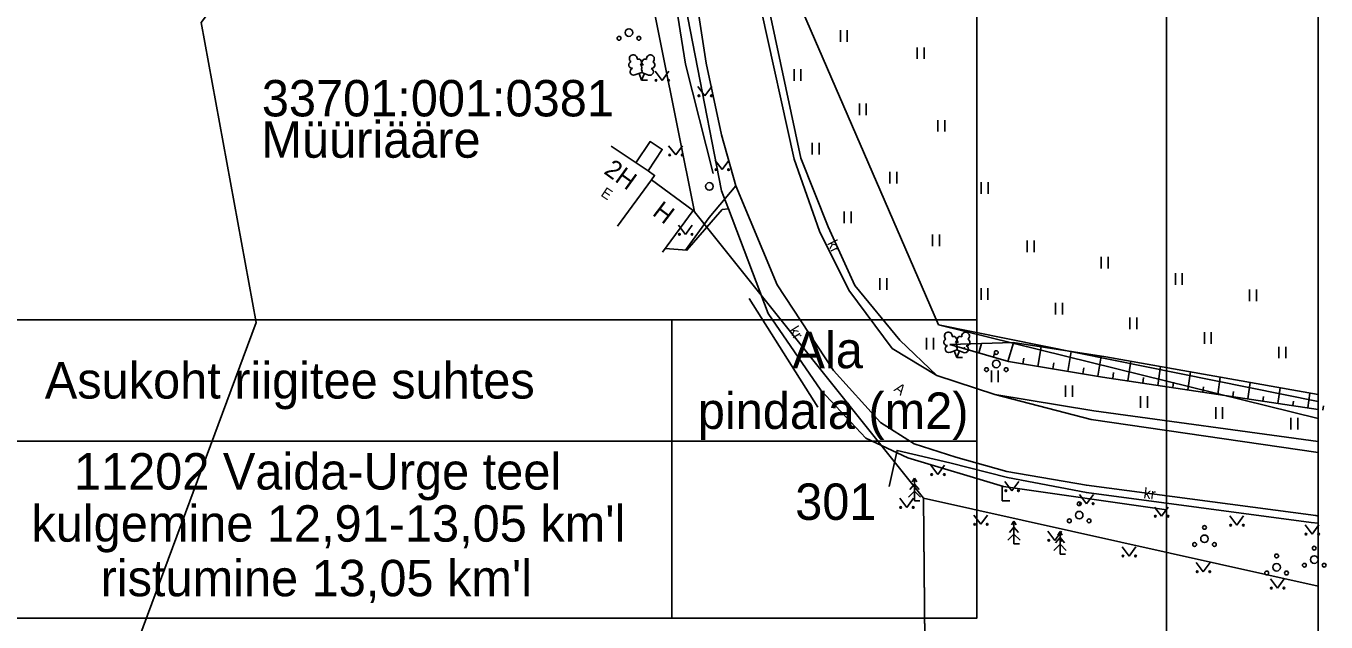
# Model space of a CAD drawing. Extents: x 554947 to 555436, y 6564938 to 6565792.
# Drawn here: x 555307.9 to 555393.6, y 6565441.5 to 6565480.8 of the extents above; entities that cross this region are included whole.
import ezdxf

# ---------------------------------------------------------------- set-up
doc = ezdxf.new("R2010")
doc.units = 0
for name, color, linetype in [('AED', 7, 'Continuous'), ('HALJASTUS', 7, 'Continuous'), ('HOONE', 7, 'Continuous'), ('HOONEDET', 7, 'Continuous'), ('PIIR', 7, 'Continuous'), ('POST', 7, 'Continuous'), ('PR_SIDE', 7, 'Continuous'), ('PUU', 7, 'Continuous'), ('RELJEEF', 7, 'Continuous'), ('TEE', 7, 'Continuous'), ('VORMISTUS_3', 7, 'Continuous')]:
    doc.layers.add(name, color=color, linetype=linetype)

msp = doc.modelspace()

# ---------------------------------------------------------------- linework, layer by layer
at = {"layer": 'AED'}
msp.add_line((555360.091, 6565455.665), (555355.569, 6565462.842), dxfattribs=at)
msp.add_lwpolyline([(555353.187, 6565471.073), (555351.365, 6565478.297), (555349.912, 6565487.399), (555348.203, 6565498.717)], dxfattribs=at)
at = {"layer": 'HALJASTUS'}
for p, q in [((555361.573, 6565480.529), (555361.573, 6565479.768)), ((555362.028, 6565480.529), (555362.028, 6565479.768)), ((555366.634, 6565479.397), (555366.634, 6565478.636)), ((555367.09, 6565479.397), (555367.09, 6565478.636)), ((555358.52, 6565477.955), (555358.52, 6565477.194)), ((555358.975, 6565477.955), (555358.975, 6565477.194)), ((555349.36, 6565477.827), (555349.824, 6565477.22)), ((555349.824, 6565477.22), (555350.269, 6565477.827)), ((555352.185, 6565476.814), (555352.649, 6565476.207)), ((555352.649, 6565476.207), (555353.094, 6565476.814)), ((555362.828, 6565475.689), (555362.828, 6565474.928)), ((555363.283, 6565475.689), (555363.283, 6565474.928)), ((555368.005, 6565474.604), (555368.005, 6565473.843)), ((555368.46, 6565474.604), (555368.46, 6565473.843)), ((555350.258, 6565472.908), (555350.722, 6565472.302)), ((555350.722, 6565472.302), (555351.167, 6565472.908)), ((555359.727, 6565473.103), (555359.727, 6565472.342)), ((555360.182, 6565473.103), (555360.182, 6565472.342)), ((555353.315, 6565471.943), (555353.779, 6565471.336)), ((555353.779, 6565471.336), (555354.224, 6565471.943)), ((555364.839, 6565471.191), (555364.839, 6565470.43)), ((555365.294, 6565471.191), (555365.294, 6565470.43)), ((555370.858, 6565470.499), (555370.858, 6565469.738)), ((555371.313, 6565470.499), (555371.313, 6565469.738)), ((555361.828, 6565468.572), (555361.828, 6565467.811)), ((555362.283, 6565468.572), (555362.283, 6565467.811)), ((555350.905, 6565467.676), (555351.368, 6565467.069)), ((555351.368, 6565467.069), (555351.814, 6565467.676)), ((555367.645, 6565467.053), (555367.645, 6565466.292)), ((555368.1, 6565467.053), (555368.1, 6565466.292)), ((555373.889, 6565466.657), (555373.889, 6565465.895)), ((555374.344, 6565466.657), (555374.344, 6565465.895)), ((555378.771, 6565465.579), (555378.771, 6565464.817)), ((555379.226, 6565465.579), (555379.226, 6565464.817)), ((555383.654, 6565464.5), (555383.654, 6565463.739)), ((555384.109, 6565464.5), (555384.109, 6565463.739)), ((555364.172, 6565464.177), (555364.172, 6565463.416)), ((555364.627, 6565464.177), (555364.627, 6565463.416)), ((555370.845, 6565463.51), (555370.845, 6565462.749)), ((555371.3, 6565463.51), (555371.3, 6565462.749)), ((555388.536, 6565463.422), (555388.536, 6565462.661)), ((555388.991, 6565463.422), (555388.991, 6565462.661)), ((555375.752, 6565462.547), (555375.752, 6565461.786)), ((555376.207, 6565462.547), (555376.207, 6565461.786)), ((555380.658, 6565461.583), (555380.658, 6565460.822)), ((555381.113, 6565461.583), (555381.113, 6565460.822)), ((555367.254, 6565460.24), (555367.254, 6565459.479)), ((555367.709, 6565460.24), (555367.709, 6565459.479)), ((555385.564, 6565460.62), (555385.564, 6565459.859)), ((555386.019, 6565460.62), (555386.019, 6565459.859)), ((555390.47, 6565459.657), (555390.47, 6565458.896)), ((555390.926, 6565459.657), (555390.926, 6565458.896)), ((555371.525, 6565458.083), (555371.525, 6565457.321)), ((555371.98, 6565458.083), (555371.98, 6565457.321)), ((555376.419, 6565457.107), (555376.419, 6565456.346)), ((555376.874, 6565457.107), (555376.874, 6565456.346)), ((555381.367, 6565456.392), (555381.367, 6565455.63)), ((555381.822, 6565456.392), (555381.822, 6565455.63)), ((555386.316, 6565455.676), (555386.316, 6565454.915)), ((555386.771, 6565455.676), (555386.771, 6565454.915)), ((555391.265, 6565454.961), (555391.265, 6565454.2)), ((555391.72, 6565454.961), (555391.72, 6565454.2)), ((555367.533, 6565451.84), (555367.997, 6565451.233)), ((555367.997, 6565451.233), (555368.442, 6565451.84)), ((555372.249, 6565450.508), (555372.249, 6565449.508)), ((555372.419, 6565450.775), (555372.882, 6565450.168)), ((555372.882, 6565450.168), (555373.328, 6565450.775)), ((555365.487, 6565449.67), (555365.951, 6565449.064)), ((555365.951, 6565449.064), (555366.396, 6565449.67)), ((555377.344, 6565449.916), (555377.807, 6565449.309)), ((555377.807, 6565449.309), (555378.253, 6565449.916)), ((555372.249, 6565449.508), (555372.749, 6565449.508)), ((555382.275, 6565449.089), (555382.738, 6565448.482)), ((555382.738, 6565448.482), (555383.184, 6565449.089)), ((555370.362, 6565448.557), (555370.825, 6565447.95)), ((555370.825, 6565447.95), (555371.271, 6565448.557)), ((555387.24, 6565448.5), (555387.703, 6565447.893)), ((555387.703, 6565447.893), (555388.149, 6565448.5)), ((555375.249, 6565447.5), (555375.712, 6565446.893)), ((555375.712, 6565446.893), (555376.158, 6565447.5)), ((555392.205, 6565447.911), (555392.669, 6565447.304)), ((555392.669, 6565447.304), (555393.114, 6565447.911)), ((555380.141, 6565446.467), (555380.604, 6565445.86)), ((555380.604, 6565445.86), (555381.05, 6565446.467)), ((555385.033, 6565445.433), (555385.496, 6565444.826)), ((555385.496, 6565444.826), (555385.942, 6565445.433)), ((555389.914, 6565444.349), (555390.377, 6565443.742)), ((555390.377, 6565443.742), (555390.823, 6565444.349))]:
    msp.add_line(p, q, dxfattribs=at)
for centre in [(555349.423, 6565477.22), (555350.251, 6565477.22), (555352.248, 6565476.207), (555353.077, 6565476.207), (555350.321, 6565472.302), (555351.15, 6565472.302), (555353.378, 6565471.336), (555354.207, 6565471.336), (555350.967, 6565467.069), (555351.796, 6565467.069), (555367.596, 6565451.233), (555368.425, 6565451.233), (555372.481, 6565450.168), (555373.31, 6565450.168), (555365.55, 6565449.064), (555366.378, 6565449.064), (555377.406, 6565449.309), (555378.235, 6565449.309), (555370.424, 6565447.95), (555371.253, 6565447.95), (555382.337, 6565448.482), (555383.166, 6565448.482), (555387.302, 6565447.893), (555388.131, 6565447.893), (555392.268, 6565447.304), (555393.096, 6565447.304), (555375.311, 6565446.893), (555376.14, 6565446.893), (555380.203, 6565445.86), (555381.032, 6565445.86), (555385.095, 6565444.826), (555385.924, 6565444.826), (555389.976, 6565443.742), (555390.805, 6565443.742)]:
    msp.add_circle(centre, 0.055, dxfattribs=at)
at = {"layer": 'HOONE'}
msp.add_line((555346.887, 6565467.616), (555349.13, 6565470.659), dxfattribs=at)
msp.add_lwpolyline([(555346.471, 6565472.875), (555348.897, 6565471.26), (555349.328, 6565470.958), (555349.13, 6565470.659), (555351.876, 6565468.634), (555349.848, 6565465.883)], dxfattribs=at)
at = {"layer": 'HOONEDET'}
msp.add_lwpolyline([(555348.897, 6565471.26), (555349.833, 6565472.665), (555349.029, 6565473.189), (555348.099, 6565471.792)], dxfattribs=at)
at = {"layer": 'PIIR'}
for points in [[(555393.069, 6565456.052), (555368.05, 6565461.11), (555358.8, 6565482.45), (555353.12, 6565523.87), (555393.069, 6565560.972)], [(555393.069, 6565443.872), (555367.06, 6565449.68), (555351.96, 6565468.55), (555343.14, 6565512.46), (555353.12, 6565523.87), (555358.8, 6565482.45), (555368.05, 6565461.11), (555393.069, 6565454.923)], [(555393.069, 6565454.923), (555368.05, 6565461.11), (555393.069, 6565456.052)], [(555367.477, 6565404.752), (555367.06, 6565449.68), (555393.069, 6565443.872)]]:
    msp.add_lwpolyline(points, dxfattribs=at)
for points in [[(555153.01, 6565448.47), (555161.15, 6565451.45), (555173.66, 6565456.03), (555207.29, 6565506.14), (555287.77, 6565518.56), (555302.6, 6565539.71), (555343.14, 6565512.46), (555319.44, 6565481.04), (555323.07, 6565461.26), (555312.9, 6565433.84), (555316.84, 6565372.52), (555318.72, 6565342.57), (555320.51, 6565314.61), (555303.13, 6565302.54), (555208.78, 6565303.3), (555205.15, 6565297.11), (555200.72, 6565310.3), (555206.9, 6565339.44), (555221.23, 6565376.06), (555216.83, 6565392.35), (555207.22, 6565406.57)], [(555319.44, 6565481.04), (555343.14, 6565512.46), (555351.96, 6565468.55), (555367.06, 6565449.68), (555367.76, 6565374.28), (555361.76, 6565374.07), (555316.84, 6565372.52), (555312.9, 6565433.84), (555323.07, 6565461.26)]]:
    msp.add_lwpolyline(points, close=True, dxfattribs=at)
at = {"layer": 'POST'}
msp.add_circle((555352.942, 6565470.231), 0.25, dxfattribs=at)
at = {"layer": 'PR_SIDE'}
for points in [[(555383.069, 6565448.914), (555372.326, 6565450.448), (555366.015, 6565452.342), (555363.26, 6565453.626), (555360.292, 6565456.785), (555356.82, 6565461.856), (555354.197, 6565468.745), (555353.746, 6565469.93), (555350.28, 6565487.806), (555348.596, 6565498.754), (555346.199, 6565508), (555346.027, 6565508.326), (555343.44, 6565510.968), (555340.158, 6565515.387), (555337.344, 6565518), (555334.369, 6565519.783), (555331.518, 6565521.47), (555329.521, 6565522.71), (555323.586, 6565526.187), (555323.123, 6565526.49), (555319.055, 6565529.304), (555309.687, 6565535.684), (555309.355, 6565535.944), (555304.351, 6565539.861)], [(555354.197, 6565468.745), (555353.785, 6565468.71), (555351.464, 6565466.022), (555350.032, 6565466.133)]]:
    msp.add_lwpolyline(points, dxfattribs=at)
at = {"layer": 'PUU'}
for p, q in [((555348.038, 6565477.576), (555348.483, 6565477.751)), ((555348.478, 6565477.241), (555348.303, 6565477.681)), ((555348.478, 6565477.241), (555348.658, 6565477.681)), ((555348.858, 6565477.241), (555348.478, 6565477.241)), ((555348.483, 6565477.751), (555348.923, 6565477.571)), ((555368.805, 6565459.287), (555369.25, 6565459.462)), ((555369.245, 6565458.952), (555369.07, 6565459.392)), ((555369.245, 6565458.952), (555369.425, 6565459.392)), ((555369.25, 6565459.462), (555369.69, 6565459.282)), ((555369.625, 6565458.952), (555369.245, 6565458.952)), ((555366.463, 6565450.595), (555366.163, 6565450.245)), ((555366.463, 6565450.995), (555366.313, 6565450.745)), ((555366.613, 6565450.745), (555366.463, 6565450.995)), ((555366.463, 6565450.995), (555366.463, 6565449.495)), ((555366.763, 6565450.245), (555366.463, 6565450.595)), ((555366.463, 6565450.145), (555366.063, 6565449.745)), ((555366.863, 6565449.745), (555366.463, 6565450.145)), ((555366.823, 6565449.495), (555366.463, 6565449.495)), ((555373.015, 6565448.158), (555372.865, 6565447.908)), ((555373.166, 6565447.908), (555373.015, 6565448.158)), ((555373.015, 6565448.158), (555373.015, 6565446.658)), ((555373.015, 6565447.308), (555372.615, 6565446.908)), ((555373.015, 6565447.758), (555372.715, 6565447.408)), ((555373.316, 6565447.408), (555373.015, 6565447.758)), ((555373.416, 6565446.908), (555373.015, 6565447.308)), ((555376.051, 6565447.081), (555375.751, 6565446.731)), ((555376.051, 6565447.481), (555375.901, 6565447.231)), ((555376.201, 6565447.231), (555376.051, 6565447.481)), ((555376.051, 6565447.481), (555376.051, 6565445.981)), ((555376.351, 6565446.731), (555376.051, 6565447.081)), ((555373.375, 6565446.658), (555373.015, 6565446.658)), ((555376.051, 6565446.631), (555375.651, 6565446.231)), ((555376.451, 6565446.231), (555376.051, 6565446.631)), ((555376.411, 6565445.981), (555376.051, 6565445.981))]:
    msp.add_line(p, q, dxfattribs=at)
for points in [[(555348.483, 6565478.246), (555348.463, 6565478.171), (555348.463, 6565478.151), (555348.473, 6565478.121), (555348.493, 6565478.086), (555348.498, 6565478.066), (555348.483, 6565478.031), (555348.458, 6565477.981), (555348.453, 6565477.956), (555348.458, 6565477.941), (555348.468, 6565477.911), (555348.503, 6565477.851), (555348.508, 6565477.831), (555348.503, 6565477.811), (555348.488, 6565477.776), (555348.483, 6565477.751)], [(555369.25, 6565459.957), (555369.23, 6565459.882), (555369.23, 6565459.862), (555369.24, 6565459.832), (555369.26, 6565459.797), (555369.265, 6565459.777), (555369.25, 6565459.742), (555369.225, 6565459.692), (555369.22, 6565459.667), (555369.225, 6565459.652), (555369.235, 6565459.622), (555369.27, 6565459.562), (555369.275, 6565459.542), (555369.27, 6565459.522), (555369.255, 6565459.487), (555369.25, 6565459.462)]]:
    msp.add_lwpolyline(points, dxfattribs=at)
for centre, radius in [((555347.639, 6565480.37), 0.25), ((555346.989, 6565479.995), 0.125), ((555348.289, 6565479.995), 0.125), ((555371.853, 6565459.273), 0.125), ((555371.203, 6565458.148), 0.125), ((555371.853, 6565458.523), 0.25), ((555372.503, 6565458.148), 0.125), ((555377.316, 6565448.554), 0.25), ((555377.316, 6565449.304), 0.125), ((555376.666, 6565448.179), 0.125), ((555377.966, 6565448.179), 0.125), ((555385.574, 6565446.994), 0.25), ((555385.574, 6565447.744), 0.125), ((555384.924, 6565446.619), 0.125), ((555386.224, 6565446.619), 0.125), ((555392.808, 6565446.376), 0.125), ((555390.326, 6565445.114), 0.25), ((555390.326, 6565445.864), 0.125), ((555392.158, 6565445.251), 0.125), ((555392.808, 6565445.626), 0.25), ((555393.458, 6565445.251), 0.125), ((555389.676, 6565444.739), 0.125), ((555390.976, 6565444.739), 0.125)]:
    msp.add_circle(centre, radius, dxfattribs=at)
for centre, radius, start, end in [((555347.921, 6565478.655), 0.256, 111.50269, 232.51731), ((555347.921, 6565478.655), 0.256, 350.48556, 111.50017), ((555349.057, 6565478.646), 0.256, 67.6168, 188.63142), ((555349.057, 6565478.646), 0.256, 306.59966, 67.61428), ((555347.847, 6565478.244), 0.224, 111.43041, 274.49868), ((555347.951, 6565477.799), 0.237, 111.50143, 291.50036), ((555348.255, 6565478.405), 0.224, 308.50412, 111.57247), ((555348.482, 6565478.008), 0.237, 66.76552, 111.50149), ((555348.718, 6565478.4), 0.225, 67.7016, 230.51262), ((555349.013, 6565477.791), 0.237, 247.61661, 67.61554), ((555349.124, 6565478.234), 0.224, 264.6183, 67.68657), ((555368.614, 6565459.955), 0.224, 111.43041, 274.49868), ((555368.688, 6565460.366), 0.256, 111.50269, 232.51731), ((555368.688, 6565460.366), 0.256, 350.48556, 111.50017), ((555369.023, 6565460.115), 0.224, 308.50412, 111.57247), ((555369.249, 6565459.719), 0.237, 66.76552, 111.50149), ((555369.486, 6565460.111), 0.225, 67.7016, 230.51262), ((555369.824, 6565460.357), 0.256, 67.6168, 188.63142), ((555369.892, 6565459.945), 0.224, 264.6183, 67.68657), ((555369.824, 6565460.357), 0.256, 306.59966, 67.61428), ((555368.719, 6565459.51), 0.237, 111.50143, 291.50036), ((555369.78, 6565459.502), 0.237, 247.61661, 67.61554)]:
    msp.add_arc(centre, radius, start, end, dxfattribs=at)
at = {"layer": 'RELJEEF'}
for p, q in [((555372.62, 6565458.694), (555372.979, 6565459.925)), ((555369.74, 6565459.534), (555369.767, 6565459.626)), ((555370.7, 6565459.254), (555370.88, 6565459.87)), ((555371.66, 6565458.974), (555371.741, 6565459.251)), ((555374.592, 6565458.362), (555374.804, 6565459.646)), ((555376.565, 6565458.036), (555376.781, 6565459.343)), ((555373.605, 6565458.525), (555373.668, 6565458.907)), ((555375.578, 6565458.199), (555375.643, 6565458.588)), ((555377.552, 6565457.873), (555377.617, 6565458.269)), ((555378.538, 6565457.71), (555378.758, 6565459.041)), ((555380.515, 6565457.409), (555380.709, 6565458.701)), ((555382.493, 6565457.112), (555382.679, 6565458.35)), ((555379.527, 6565457.557), (555379.586, 6565457.953)), ((555381.504, 6565457.261), (555381.561, 6565457.64)), ((555384.471, 6565456.816), (555384.649, 6565457.999)), ((555386.449, 6565456.519), (555386.618, 6565457.648)), ((555383.482, 6565456.964), (555383.537, 6565457.327)), ((555385.46, 6565456.667), (555385.512, 6565457.014)), ((555387.438, 6565456.371), (555387.488, 6565456.701)), ((555388.427, 6565456.222), (555388.588, 6565457.297)), ((555390.405, 6565455.926), (555390.558, 6565456.946)), ((555392.383, 6565455.629), (555392.528, 6565456.595)), ((555389.416, 6565456.074), (555389.463, 6565456.388)), ((555391.394, 6565455.777), (555391.438, 6565456.075)), ((555393.372, 6565455.481), (555393.414, 6565455.762))]:
    msp.add_line(p, q, dxfattribs=at)
for points in [[(555368.78, 6565459.814), (555372.971, 6565459.927), (555379.063, 6565458.994), (555393.069, 6565456.498)], [(555368.78, 6565459.814), (555372.666, 6565458.68), (555378.843, 6565457.66), (555393.069, 6565455.526)]]:
    msp.add_lwpolyline(points, dxfattribs=at)
at = {"layer": 'TEE'}
for points in [[(555360.017, 6565532.032), (555356.722, 6565529.611), (555352.039, 6565526.571), (555350.841, 6565524.289), (555349.902, 6565522.246), (555349.37, 6565518.742), (555349.968, 6565514.969), (555351.498, 6565509.514), (555352.399, 6565505.44), (555355.185, 6565489.693), (555356.356, 6565481.874), (555358.536, 6565472.027), (555360.203, 6565467.288), (555362.127, 6565463.387), (555364.998, 6565459.532), (555367.923, 6565457.754), (555371.76, 6565456.513), (555378.11, 6565454.853), (555393.069, 6565452.684)], [(555393.069, 6565448.493), (555392.904, 6565448.521), (555377.792, 6565450.52), (555372.547, 6565451.424), (555369.187, 6565452.37), (555366.443, 6565453.255), (555364.23, 6565454.662), (555361.13, 6565458.083), (555357.411, 6565463.749), (555354.693, 6565470.258), (555353.748, 6565473.64), (555352.733, 6565478.362), (555351.267, 6565487.961), (555349.516, 6565498.784), (555347.141, 6565508.358), (555345.332, 6565511.802), (555341.773, 6565516.752), (555338.53, 6565519.62), (555330.669, 6565524.333), (555325.029, 6565527.171), (555324.447, 6565527.997), (555320.204, 6565530.941)], [(555358.969, 6565483.478), (555358.843, 6565483.458), (555356.63, 6565483.037), (555358.965, 6565472.102), (555360.762, 6565467.568), (555362.536, 6565463.692), (555365.5, 6565460.084), (555367.923, 6565457.754)], [(555351.364, 6565466.022), (555352.93, 6565468.179), (555354.693, 6565470.258)], [(555371.76, 6565456.513), (555378.274, 6565455.429), (555393.069, 6565453.404)], [(555393.069, 6565448.031), (555392.602, 6565448.077), (555377.792, 6565450.042), (555372.591, 6565451.027), (555368.793, 6565452.002), (555365.308, 6565452.827), (555364.788, 6565450.448)]]:
    msp.add_lwpolyline(points, dxfattribs=at)
at = {"layer": 'VORMISTUS_3'}
for p, q in [((555350.469, 6565461.442), (555350.469, 6565441.752)), ((555350.469, 6565461.442), (555350.469, 6565441.752)), ((555205.569, 6565453.442), (555370.569, 6565453.442))]:
    msp.add_line(p, q, dxfattribs=at)
for points in [[(555183.069, 6565701.752), (555393.069, 6565701.752), (555393.069, 6565404.752), (555183.069, 6565404.752)], [(555193.069, 6565415.752), (555383.069, 6565415.752), (555383.069, 6565690.752), (555193.069, 6565690.752)], [(555193.069, 6565690.752), (555383.069, 6565690.752), (555383.069, 6565415.752), (555193.069, 6565415.752)], [(555370.569, 6565441.752), (555205.569, 6565441.752), (555205.569, 6565651.752), (555370.569, 6565651.752)], [(555205.569, 6565461.442), (555370.569, 6565461.442), (555370.569, 6565441.752), (555205.569, 6565441.752)]]:
    msp.add_lwpolyline(points, close=True, dxfattribs=at)

# ---------------------------------------------------------------- texts
at = {"layer": 'HOONE'}
for s, height, rotation, p in [('2H', 1.2, 324.17294, (555345.923, 6565471.127)), ('E', 0.7, 326.34193, (555345.732, 6565469.638)), ('H', 1.2, 322.94839, (555349.121, 6565468.379))]:
    msp.add_text(s, height=height, rotation=rotation, dxfattribs=at).set_placement(p)
at = {"layer": 'PIIR'}
for s, p in [('33701:001:0381', (555323.446, 6565474.845)), ('Müüriääre', (555323.415, 6565472.122))]:
    msp.add_text(s, height=2.4, dxfattribs=at).set_placement(p)
at = {"layer": 'TEE'}
for s, rotation, p in [('kr', 296.21546, (555360.69, 6565466.483)), ('kr', 302.10529, (555358.156, 6565460.742)), ('A', 323.81797, (555365.054, 6565456.781)), ('kr', 352.39623, (555381.529, 6565449.681))]:
    msp.add_text(s, height=0.7, rotation=rotation, dxfattribs=at).set_placement(p)
at = {"layer": 'VORMISTUS_3'}
for s, p in [('Ala', (555358.42, 6565458.242)), ('Asukoht riigitee suhtes ', (555309.141, 6565456.242)), ('pindala (m2)', (555352.181, 6565454.242)), ('11202 Vaida-Urge teel', (555311.061, 6565450.242)), ('301', (555358.6, 6565448.242)), ("kulgemine 12,91-13,05 km'l", (555308.258, 6565446.806)), ("ristumine 13,05 km'l", (555312.818, 6565443.206))]:
    msp.add_text(s, height=2.4, dxfattribs=at).set_placement(p)

doc.saveas('drawing.dxf')
